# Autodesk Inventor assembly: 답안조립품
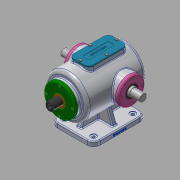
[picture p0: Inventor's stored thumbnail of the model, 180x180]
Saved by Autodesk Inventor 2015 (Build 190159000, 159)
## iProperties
Created: 2021-11
Part Number: 답안조립품
Document SubType Name: Assembly
Designer: 102879
Author: 102879
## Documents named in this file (14)
- C:\Users\102879\Desktop\711106V1016\답안조립품.iam
- C:\Users\102879\Desktop\711106V1016\베어링 6205.ipt
- 베어링 6205.ipt
- C:\Users\102879\Desktop\711106V1016\본체.ipt
- C:\Users\102879\Desktop\711106V1016\볼트 M4x0.7.ipt
- C:\Users\102879\Desktop\711106V1016\부시.ipt
- C:\Users\102879\Desktop\711106V1016\상부커버.ipt
- C:\Users\102879\Desktop\711106V1016\슬라이드 커버.ipt
- C:\Users\102879\Desktop\711106V1016\슬라이드.ipt
- C:\Users\102879\Desktop\711106V1016\오일실.ipt
- 오일실.ipt
- C:\Users\102879\Desktop\711106V1016\육각머리볼트 M4.ipt
- C:\Users\102879\Desktop\711106V1016\축 커버.ipt
- C:\Users\102879\Desktop\711106V1016\편심축.ipt
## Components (12 placed, 1 different names)
1. M4x0.7:1
2. M4x0.7:4
3. M4x0.7:5
4. M4x0.7:6
5. M4x0.7:3
6. M4x0.7:7
7. M4x0.7:8
8. M4x0.7:9
9. M4x0.7:2
10. M4x0.7:10
11. M4x0.7:11
12. M4x0.7:12
